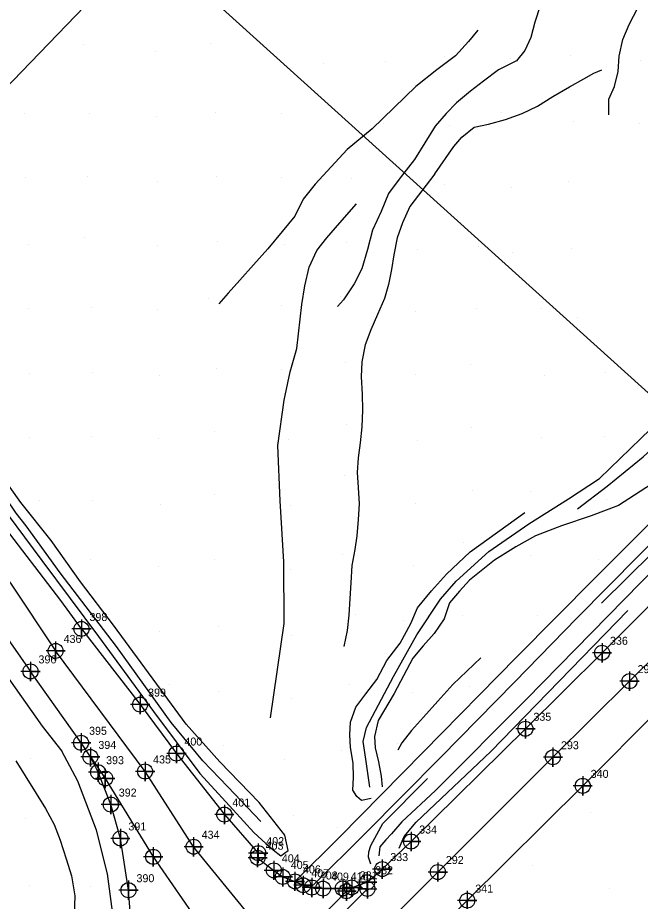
# Model space of a CAD drawing. Extents: x 1497074 to 1501343, y 481943 to 486114.
# Drawn here: x 1499153.8 to 1499348.3, y 485629.8 to 485905.8 of the extents above; entities that cross this region are included whole.
import ezdxf

# ---------------------------------------------------------------- set-up
doc = ezdxf.new("R2010")
doc.units = 0
for name, color, linetype in [('Exist DTM Breakline', 7, 'Continuous'), ('Exist DTM Breakline Cogo Point CELL', 7, 'Continuous'), ('Exist DTM Crownline', 7, 'Continuous'), ('Exist DTM Crownline Cogo Number', 7, 'Continuous'), ('Exist DTM Crownline Cogo Point CELL', 7, 'Continuous'), ('Exist Roads EOP', 7, 'Continuous'), ('Exist Roads EOP Cogo Number', 7, 'Continuous'), ('Exist Roads EOP Cogo Point CELL', 7, 'Continuous'), ('Exist Roads EOT', 7, 'Continuous'), ('Exist Roads EOT Cogo Point CELL', 7, 'Continuous'), ('PH Exist DTM Boundary', 7, 'Continuous'), ('PH Exist DTM Breakline', 7, 'Continuous'), ('PH Exist DTM Point', 7, 'Continuous')]:
    doc.layers.add(name, color=color, linetype=linetype)

msp = doc.modelspace()

# ---------------------------------------------------------------- linework, layer by layer
at = {"layer": 'Exist DTM Breakline'}
for points in [[(1499176.46, 485674.88), (1499181.12, 485668.19), (1499196.1, 485643.7), (1499211.18, 485621.88)], [(1499222.35, 485598.56), (1499236.31, 485612.27), (1499256.47, 485632.94)]]:
    msp.add_lwpolyline(points, dxfattribs=at)
at = {"layer": 'Exist DTM Breakline Cogo Point CELL'}
for points in [[(1499181.12, 485671.19), (1499181.12, 485665.19), (1499181.12, 485668.19), (1499184.12, 485668.19), (1499178.12, 485668.19)], [(1499196.1, 485646.7), (1499196.1, 485640.7), (1499196.1, 485643.7), (1499199.1, 485643.7), (1499193.1, 485643.7)], [(1499256.47, 485635.94), (1499256.47, 485629.94), (1499256.47, 485632.94), (1499259.47, 485632.94), (1499253.47, 485632.94)]]:
    msp.add_lwpolyline(points, dxfattribs=at)
for centre in [(1499181.12, 485668.19), (1499196.1, 485643.7), (1499256.47, 485632.94)]:
    msp.add_circle(centre, 2.34, dxfattribs=at)
at = {"layer": 'Exist DTM Crownline'}
for points in [[(1498753.92, 485018.83), (1498767.97, 485036.35), (1498784.41, 485057.61), (1498813.33, 485094.71), (1498845.11, 485135.39), (1498876.05, 485175.22), (1498907.7, 485215.72), (1498939.87, 485257.15), (1498970.73, 485296.32), (1499001.6, 485335.5), (1499032.55, 485374.36), (1499053.88, 485400.5), (1499073.91, 485423.48), (1499090.49, 485441.64), (1499112.37, 485464.57), (1499148.43, 485501.47), (1499184.54, 485537.77), (1499215.93, 485569.25), (1499248.51, 485602.52), (1499285.02, 485638.96), (1499320.99, 485674.8), (1499344.91, 485698.57), (1499374.04, 485727.35), (1499398.21, 485750.96)], [(1499235.5, 485614.5), (1499226.83, 485624.63), (1499208.73, 485646.85), (1499193.56, 485670.36), (1499165.61, 485707.99)]]:
    msp.add_lwpolyline(points, dxfattribs=at)
at = {"layer": 'Exist DTM Crownline Cogo Point CELL'}
for points in [[(1499165.61, 485710.99), (1499165.61, 485704.99), (1499165.61, 485707.99), (1499168.61, 485707.99), (1499162.61, 485707.99)], [(1499344.91, 485701.57), (1499344.91, 485695.57), (1499344.91, 485698.57), (1499347.91, 485698.57), (1499341.91, 485698.57)], [(1499320.99, 485677.8), (1499320.99, 485671.8), (1499320.99, 485674.8), (1499323.99, 485674.8), (1499317.99, 485674.8)], [(1499193.56, 485673.36), (1499193.56, 485667.36), (1499193.56, 485670.36), (1499196.56, 485670.36), (1499190.56, 485670.36)], [(1499208.73, 485649.85), (1499208.73, 485643.85), (1499208.73, 485646.85), (1499211.73, 485646.85), (1499205.73, 485646.85)], [(1499285.02, 485641.96), (1499285.02, 485635.96), (1499285.02, 485638.96), (1499288.02, 485638.96), (1499282.02, 485638.96)]]:
    msp.add_lwpolyline(points, dxfattribs=at)
for centre in [(1499165.61, 485707.99), (1499344.91, 485698.57), (1499320.99, 485674.8), (1499193.56, 485670.36), (1499208.73, 485646.85), (1499285.02, 485638.96)]:
    msp.add_circle(centre, 2.34, dxfattribs=at)
at = {"layer": 'Exist Roads EOP'}
for points in [[(1499258.1, 485634.16), (1499262.94, 485635.76), (1499267.66, 485639.88), (1499276.68, 485648.48), (1499312.38, 485683.69), (1499336.31, 485707.42), (1499365.12, 485736.27), (1499388.62, 485759.64)], [(1499406.68, 485742.77), (1499382.28, 485717.88), (1499354.16, 485689.77), (1499330.28, 485665.86), (1499294.21, 485630.03), (1499257.75, 485593.24), (1499238.22, 485573.68), (1499232.58, 485566.91), (1499223.56, 485558.73), (1499194.15, 485529.24), (1499157.4, 485492.59), (1499121.26, 485455.44)], [(1499173.68, 485714.85), (1499192, 485691.24), (1499203.35, 485675.95), (1499218.32, 485656.9), (1499228.92, 485644.84), (1499228.72, 485643.43), (1499233.78, 485639.48), (1499236.57, 485637.41), (1499240.39, 485636.03), (1499242.98, 485634.81), (1499245.65, 485634.12), (1499249.15, 485633.78), (1499255.31, 485633.84), (1499258.1, 485634.16)], [(1499172.31, 485548.88), (1499179.71, 485562.65), (1499184.8, 485580.27), (1499188.78, 485607.06), (1499189.23, 485622.67), (1499188.38, 485633.27), (1499185.84, 485649.44), (1499182.84, 485660.02), (1499178.88, 485670.13), (1499176.46, 485674.89), (1499173.56, 485679.31), (1499157.76, 485701.6)]]:
    msp.add_lwpolyline(points, dxfattribs=at)
at = {"layer": 'Exist Roads EOP Cogo Point CELL'}
for points in [[(1499173.68, 485717.85), (1499173.68, 485711.85), (1499173.68, 485714.85), (1499176.68, 485714.85), (1499170.68, 485714.85)], [(1499336.31, 485710.42), (1499336.31, 485704.42), (1499336.31, 485707.42), (1499339.31, 485707.42), (1499333.31, 485707.42)], [(1499157.76, 485704.6), (1499157.76, 485698.6), (1499157.76, 485701.6), (1499160.76, 485701.6), (1499154.76, 485701.6)], [(1499192, 485694.24), (1499192, 485688.24), (1499192, 485691.24), (1499195, 485691.24), (1499189, 485691.24)], [(1499312.38, 485686.69), (1499312.38, 485680.69), (1499312.38, 485683.69), (1499315.38, 485683.69), (1499309.38, 485683.69)], [(1499173.56, 485682.31), (1499173.56, 485676.31), (1499173.56, 485679.31), (1499176.56, 485679.31), (1499170.56, 485679.31)], [(1499176.46, 485677.89), (1499176.46, 485671.89), (1499176.46, 485674.89), (1499179.46, 485674.89), (1499173.46, 485674.89)], [(1499203.35, 485678.95), (1499203.35, 485672.95), (1499203.35, 485675.95), (1499206.35, 485675.95), (1499200.35, 485675.95)], [(1499178.88, 485673.13), (1499178.88, 485667.13), (1499178.88, 485670.13), (1499181.88, 485670.13), (1499175.88, 485670.13)], [(1499330.28, 485668.86), (1499330.28, 485662.86), (1499330.28, 485665.86), (1499333.28, 485665.86), (1499327.28, 485665.86)], [(1499182.84, 485663.02), (1499182.84, 485657.02), (1499182.84, 485660.02), (1499185.84, 485660.02), (1499179.84, 485660.02)], [(1499218.32, 485659.9), (1499218.32, 485653.9), (1499218.32, 485656.9), (1499221.32, 485656.9), (1499215.32, 485656.9)], [(1499185.84, 485652.44), (1499185.84, 485646.44), (1499185.84, 485649.44), (1499188.84, 485649.44), (1499182.84, 485649.44)], [(1499276.68, 485651.48), (1499276.68, 485645.48), (1499276.68, 485648.48), (1499279.68, 485648.48), (1499273.68, 485648.48)], [(1499228.92, 485647.84), (1499228.92, 485641.84), (1499228.92, 485644.84), (1499231.92, 485644.84), (1499225.92, 485644.84)], [(1499228.72, 485646.43), (1499228.72, 485640.43), (1499228.72, 485643.43), (1499231.72, 485643.43), (1499225.72, 485643.43)], [(1499233.78, 485642.48), (1499233.78, 485636.48), (1499233.78, 485639.48), (1499236.78, 485639.48), (1499230.78, 485639.48)], [(1499267.66, 485642.88), (1499267.66, 485636.88), (1499267.66, 485639.88), (1499270.66, 485639.88), (1499264.66, 485639.88)], [(1499236.57, 485640.41), (1499236.57, 485634.41), (1499236.57, 485637.41), (1499239.57, 485637.41), (1499233.57, 485637.41)], [(1499240.39, 485639.03), (1499240.39, 485633.03), (1499240.39, 485636.03), (1499243.39, 485636.03), (1499237.39, 485636.03)], [(1499188.38, 485636.27), (1499188.38, 485630.27), (1499188.38, 485633.27), (1499191.38, 485633.27), (1499185.38, 485633.27)], [(1499242.98, 485637.81), (1499242.98, 485631.81), (1499242.98, 485634.81), (1499245.98, 485634.81), (1499239.98, 485634.81)], [(1499245.65, 485637.12), (1499245.65, 485631.12), (1499245.65, 485634.12), (1499248.65, 485634.12), (1499242.65, 485634.12)], [(1499249.15, 485636.78), (1499249.15, 485630.78), (1499249.15, 485633.78), (1499252.15, 485633.78), (1499246.15, 485633.78)], [(1499255.31, 485636.84), (1499255.31, 485630.84), (1499255.31, 485633.84), (1499258.31, 485633.84), (1499252.31, 485633.84)], [(1499258.1, 485637.16), (1499258.1, 485631.16), (1499258.1, 485634.16), (1499261.1, 485634.16), (1499255.1, 485634.16)], [(1499262.94, 485638.76), (1499262.94, 485632.76), (1499262.94, 485635.76), (1499265.94, 485635.76), (1499259.94, 485635.76)], [(1499294.21, 485633.03), (1499294.21, 485627.03), (1499294.21, 485630.03), (1499297.21, 485630.03), (1499291.21, 485630.03)]]:
    msp.add_lwpolyline(points, dxfattribs=at)
for centre in [(1499173.68, 485714.85), (1499336.31, 485707.42), (1499157.76, 485701.6), (1499192, 485691.24), (1499312.38, 485683.69), (1499173.56, 485679.31), (1499203.35, 485675.95), (1499176.46, 485674.89), (1499178.88, 485670.13), (1499330.28, 485665.86), (1499182.84, 485660.02), (1499218.32, 485656.9), (1499185.84, 485649.44), (1499276.68, 485648.48), (1499228.92, 485644.84), (1499228.72, 485643.43), (1499233.78, 485639.48), (1499267.66, 485639.88), (1499236.57, 485637.41), (1499240.39, 485636.03), (1499242.98, 485634.81), (1499245.65, 485634.12), (1499249.15, 485633.78), (1499255.31, 485633.84), (1499258.1, 485634.16), (1499262.94, 485635.76), (1499188.38, 485633.27), (1499294.21, 485630.03)]:
    msp.add_circle(centre, 2.34, dxfattribs=at)
at = {"layer": 'Exist Roads EOT'}
msp.add_lwpolyline([(1499164.74, 485535.21), (1499193.9, 485564.62), (1499219.81, 485590.53), (1499263, 485633.7)], dxfattribs=at)
at = {"layer": 'Exist Roads EOT Cogo Point CELL'}
msp.add_lwpolyline([(1499263, 485636.7), (1499263, 485630.7), (1499263, 485633.7), (1499260, 485633.7), (1499266, 485633.7)], dxfattribs=at)
msp.add_circle((1499263, 485633.7), 2.34, dxfattribs=at)
at = {"layer": 'PH Exist DTM Boundary'}
for points in [[(1499194.3, 485929.74), (1499565.8, 485594.67), (1499665.72, 485698.27), (1499305.84, 486045.38)], [(1498846.5, 485569.16), (1499227.59, 485244.03), (1499565.8, 485594.67), (1499194.3, 485929.74)]]:
    msp.add_lwpolyline(points, close=True, dxfattribs=at)
at = {"layer": 'PH Exist DTM Breakline'}
for points in [[(1499338.41, 485875.42), (1499338.43, 485880.26), (1499340.17, 485884.29), (1499341.34, 485888.91), (1499341.71, 485893.71), (1499342.78, 485898.91), (1499344.79, 485903.6), (1499347.49, 485908.81), (1499351.23, 485915.07), (1499354.84, 485920.58), (1499359.06, 485926.29), (1499363.76, 485931.87), (1499368.81, 485937.66), (1499373.27, 485942.79), (1499377.18, 485947.28)], [(1499327.33, 485933.42), (1499326.69, 485928.46), (1499325.21, 485923.81), (1499322.6, 485918.77), (1499319.45, 485913.65), (1499316.97, 485909.47), (1499315.29, 485904.37), (1499314.03, 485899.55), (1499312.24, 485895.47), (1499309.58, 485892.31), (1499304.01, 485889.43), (1499299.24, 485885.89), (1499295.19, 485882.76), (1499290.86, 485879.21), (1499287.61, 485875.84), (1499284.17, 485871.89), (1499277.77, 485861.5)], [(1499297.54, 485901.82), (1499294.61, 485898.27), (1499290.49, 485893.86), (1499284.66, 485889.47), (1499278.17, 485884.27), (1499264.46, 485871.05)], [(1499284.13, 485856.97), (1499289.98, 485865.49), (1499292.51, 485868.39), (1499296.34, 485871.54), (1499300.82, 485872.52), (1499306.12, 485873.92), (1499311.4, 485875.83), (1499316.13, 485878.07), (1499320.94, 485881.15), (1499326.14, 485884.16), (1499330.62, 485886.7), (1499333.76, 485888.47), (1499336.25, 485889.5)], [(1499264.46, 485871.05), (1499256.72, 485864.62), (1499246.72, 485853.79), (1499242.93, 485849.11), (1499240.3, 485843.72), (1499236.34, 485838.99), (1499231.9, 485833.59), (1499227.48, 485828.61), (1499223.21, 485823.83), (1499219.55, 485819.73), (1499216.61, 485816.44)], [(1499277.77, 485861.5), (1499273.21, 485855.76), (1499269.59, 485850.8), (1499267.33, 485845.23), (1499264.64, 485839.37), (1499263.05, 485833.35), (1499261.32, 485827.28), (1499258.85, 485822.61), (1499255.58, 485817.63), (1499253.7, 485815.51)], [(1499284.13, 485856.97), (1499276.25, 485846.82), (1499273.94, 485841.68), (1499272.31, 485836.96), (1499271.24, 485831.74), (1499270.54, 485827.07), (1499269.58, 485822.44), (1499268.39, 485818.07), (1499266.2, 485813.11), (1499264.05, 485808.3), (1499262.35, 485803.61), (1499261.26, 485798.26), (1499261.06, 485793.57), (1499261.33, 485788.15), (1499261.49, 485783.23), (1499261.28, 485778.01), (1499260.75, 485772.99), (1499260.17, 485768.34), (1499259.85, 485763.74), (1499260.12, 485759.01), (1499260.47, 485753.98), (1499260.13, 485749.09), (1499259.73, 485743.99), (1499259.11, 485739.65), (1499258.18, 485734.69), (1499257.8, 485729.26), (1499257.51, 485724.32), (1499257.21, 485719.2), (1499256.7, 485714.42), (1499255.62, 485709.34)], [(1499232.75, 485687.11), (1499236.96, 485716.58), (1499236.87, 485735.8), (1499235.81, 485754.83), (1499235.04, 485772.12), (1499237, 485786.31), (1499238.87, 485795.11), (1499240.93, 485802.43), (1499242.51, 485816.15), (1499243.42, 485822.06), (1499244.78, 485827.84), (1499247.17, 485833.08), (1499250.31, 485837.03), (1499254.45, 485841.67), (1499259.63, 485847.61)], [(1499229.71, 485654.73), (1499219.4, 485665.56), (1499211.63, 485673.64), (1499201.76, 485685.6), (1499184.63, 485709.35), (1499167.01, 485732.42), (1499156.46, 485747.1), (1499153.27, 485751), (1499146.89, 485760.3), (1499132.38, 485780.87), (1499119.27, 485800.79), (1499104.73, 485823.72), (1499094.44, 485837.33)], [(1499173.68, 485714.85), (1499167.19, 485723.77), (1499148.64, 485748.11), (1499130.51, 485772.13), (1499116, 485791.04), (1499097.67, 485814.77), (1499085.19, 485830.54)], [(1499077.06, 485824.55), (1499092.45, 485805.28), (1499108.65, 485784.4), (1499127.38, 485760.11), (1499151.53, 485729.14), (1499165.61, 485707.99)], [(1499068.97, 485817.49), (1499083.05, 485799.83), (1499099.09, 485779.44), (1499114.5, 485759.1), (1499129.89, 485739.82), (1499148.38, 485715), (1499157.76, 485701.6)], [(1499263.77, 485665.44), (1499262.49, 485674.17), (1499261.7, 485679.68), (1499262.71, 485684.08), (1499271.15, 485700.06), (1499278.47, 485713.07), (1499285.81, 485724.17), (1499290.79, 485729.75), (1499300.92, 485739.04), (1499313.47, 485747.72), (1499325.83, 485755.49), (1499335.56, 485761.87), (1499348.39, 485774.33), (1499360.19, 485785.69), (1499365.26, 485790.69)], [(1499328.66, 485752.34), (1499337.96, 485759.47), (1499349.18, 485768.58), (1499359.28, 485777.86), (1499366.41, 485784.67)], [(1499373.87, 485780.29), (1499353.21, 485761.01), (1499341.44, 485753.44), (1499332.9, 485750.22), (1499323.66, 485747.02), (1499315.58, 485743.93), (1499309.41, 485740.52), (1499302.75, 485736.38), (1499294.89, 485730.11), (1499291.82, 485726.68), (1499288.66, 485723.02), (1499286.96, 485718.06), (1499283.92, 485713.48), (1499280.48, 485709.62), (1499277.23, 485705.77), (1499271.39, 485694.69), (1499266.38, 485686.26), (1499265.24, 485681.28), (1499265.46, 485677.78), (1499266.5, 485673.41), (1499267.31, 485668.86), (1499267.59, 485665.59)], [(1499377.52, 485774.37), (1499356.71, 485753.35), (1499334.21, 485730.82), (1499309.75, 485706.2), (1499280.46, 485676.39), (1499254.43, 485649.91), (1499240.48, 485636.07)], [(1499145.27, 485757.67), (1499161.28, 485736.27), (1499179.04, 485712.53), (1499196.18, 485689.05), (1499210.64, 485669.68), (1499221.03, 485658.39), (1499227.54, 485651.26), (1499231.29, 485647.91), (1499233.53, 485645.91), (1499236.01, 485643.98), (1499238.21, 485645.65), (1499237.23, 485650.46), (1499229.16, 485660.65), (1499216.9, 485673.4), (1499206.35, 485685.12), (1499197.22, 485697.58), (1499183.7, 485716.02), (1499173.39, 485729.55), (1499164.23, 485742.44), (1499154.78, 485754.38), (1499141.8, 485772.4)], [(1499246.03, 485634.9), (1499262.18, 485650.84), (1499285.92, 485674.84), (1499308.93, 485698.23), (1499328.52, 485718.3), (1499347.84, 485737.84), (1499368.19, 485758.34), (1499381.05, 485771.3)], [(1499381.7, 485766.98), (1499360.14, 485746.52), (1499336.2, 485722.89)], [(1499383.77, 485765.01), (1499353.48, 485734.44), (1499312.69, 485692.97), (1499284.3, 485664.38), (1499273.79, 485654.58), (1499270.53, 485650.93), (1499268.82, 485649.01), (1499266.93, 485646.77), (1499266.57, 485644.06)], [(1499264.15, 485661.96), (1499261.2, 485661.32), (1499259.75, 485662.5), (1499258.46, 485664.56), (1499258.71, 485668.44), (1499258.61, 485672.96), (1499257.75, 485677.8), (1499257.52, 485681.75), (1499257.71, 485685.75), (1499259.36, 485690.44), (1499262.48, 485694.63), (1499265.98, 485699.1), (1499269.09, 485705.06), (1499273.23, 485710.39), (1499276.57, 485716.59), (1499278.64, 485721.42), (1499283, 485726.72), (1499287.71, 485731.99), (1499295.08, 485738.92), (1499312.24, 485751.18)], [(1499125.55, 485735.22), (1499161.44, 485684.5), (1499167.54, 485676.72)], [(1499272.91, 485646.45), (1499274.48, 485650.08), (1499278.3, 485654.49), (1499301.54, 485676.58), (1499344.35, 485720.67)], [(1499298.41, 485705.89), (1499289.66, 485697.52), (1499284.98, 485692.27), (1499280.57, 485687.33), (1499276.8, 485683.12), (1499273.79, 485679.31), (1499272.56, 485677.04)], [(1499177.87, 485578.72), (1499178.98, 485584.56), (1499179.92, 485588.38), (1499181.37, 485590.01), (1499183.81, 485596.7), (1499183.46, 485616.03), (1499183.43, 485626.6), (1499181.81, 485638.44), (1499178.36, 485652.05), (1499172.58, 485667.36), (1499167.54, 485676.72)], [(1499153.17, 485673.71), (1499162.45, 485658.84), (1499165.18, 485653.77), (1499167.02, 485648.89), (1499168.88, 485643.09), (1499170.56, 485637.72), (1499171.57, 485631.53), (1499171.4, 485625.48), (1499170.63, 485618.57), (1499170.84, 485611.93), (1499171.01, 485605.52), (1499171.2, 485599.72), (1499170.74, 485593.96), (1499169.59, 485586.49), (1499169.76, 485581.42), (1499170.2, 485576.57), (1499167.23, 485571.91), (1499158.21, 485562.48), (1499132.52, 485536.14)], [(1499264.07, 485641.38), (1499263.31, 485643.56), (1499263.44, 485645.29), (1499264.07, 485647.28), (1499267.83, 485654.09), (1499281.74, 485668.16)]]:
    msp.add_lwpolyline(points, dxfattribs=at)
at = {"layer": 'PH Exist DTM Point'}
for p, q in [((1499174.39, 485897.39), (1499174.39, 485897.39)), ((1499214.12, 485897.63), (1499214.12, 485897.63)), ((1499196.83, 485895.21), (1499196.83, 485895.21)), ((1499286.98, 485893.61), (1499286.98, 485893.61)), ((1499307.6, 485893.07), (1499307.6, 485893.07)), ((1499326.49, 485894.06), (1499326.49, 485894.06)), ((1499249.38, 485891.5), (1499249.38, 485891.5)), ((1499268.63, 485892.17), (1499268.63, 485892.17)), ((1499348.25, 485892.51), (1499348.25, 485892.51)), ((1499215.67, 485876.23), (1499215.67, 485876.23)), ((1499156.04, 485875.92), (1499156.04, 485875.92)), ((1499176.04, 485875.92), (1499176.04, 485875.92)), ((1499197.08, 485874.99), (1499197.08, 485874.99)), ((1499236.04, 485875.92), (1499236.04, 485875.92)), ((1499304.84, 485876.01), (1499304.84, 485876.01)), ((1499268.2, 485872.55), (1499268.2, 485872.55)), ((1499288.66, 485872.15), (1499288.66, 485872.15)), ((1499327.28, 485873.42), (1499327.28, 485873.42)), ((1499348.05, 485872.68), (1499348.05, 485872.68)), ((1499156.26, 485855.72), (1499156.26, 485855.72)), ((1499175.6, 485856.31), (1499175.6, 485856.31)), ((1499197.43, 485854.68), (1499197.43, 485854.68)), ((1499215.88, 485856.06), (1499215.88, 485856.06)), ((1499236.04, 485855.92), (1499236.04, 485855.92)), ((1499258.09, 485855.67), (1499258.09, 485855.67)), ((1499276.7, 485855.33), (1499276.7, 485855.33)), ((1499325.88, 485854.57), (1499325.88, 485854.57)), ((1499287.04, 485853.56), (1499287.04, 485853.56)), ((1499307.96, 485852.76), (1499307.96, 485852.76)), ((1499157.18, 485834.9), (1499157.18, 485834.9)), ((1499174.73, 485837.09), (1499174.73, 485837.09)), ((1499216.03, 485835.92), (1499216.03, 485835.92)), ((1499237, 485835.06), (1499237, 485835.06)), ((1499256.5, 485835.56), (1499256.5, 485835.56)), ((1499197.35, 485834.74), (1499197.35, 485834.74)), ((1499278.78, 485833.47), (1499278.78, 485833.47)), ((1499297.82, 485834.33), (1499297.82, 485834.33)), ((1499308.42, 485832.36), (1499308.42, 485832.36)), ((1499326.92, 485833.66), (1499326.92, 485833.66)), ((1499254.49, 485818.66), (1499254.49, 485818.66)), ((1499213.47, 485818.21), (1499213.47, 485818.21)), ((1499236.04, 485815.92), (1499236.04, 485815.92)), ((1499157.2, 485814.88), (1499157.2, 485814.88)), ((1499176.81, 485815.23), (1499176.81, 485815.23)), ((1499197.44, 485814.67), (1499197.44, 485814.67)), ((1499278.12, 485814.05), (1499278.12, 485814.05)), ((1499297.13, 485814.97), (1499297.13, 485814.97)), ((1499317.28, 485814.81), (1499317.28, 485814.81)), ((1499328.58, 485812.22), (1499328.58, 485812.22)), ((1499256.3, 485798.02), (1499256.3, 485798.02)), ((1499295.18, 485797.45), (1499295.18, 485797.45)), ((1499157.56, 485794.56), (1499157.56, 485794.56)), ((1499177.14, 485794.93), (1499177.14, 485794.93)), ((1499198.03, 485794.14), (1499198.03, 485794.14)), ((1499215.83, 485796.1), (1499215.83, 485796.1)), ((1499236.06, 485795.9), (1499236.06, 485795.9)), ((1499277.98, 485794.18), (1499277.98, 485794.18)), ((1499318.3, 485793.9), (1499318.3, 485793.9)), ((1499337.37, 485794.9), (1499337.37, 485794.9)), ((1499256.35, 485778.57), (1499256.35, 485778.57)), ((1499295.62, 485777.8), (1499295.62, 485777.8)), ((1499157.49, 485774.63), (1499157.49, 485774.63)), ((1499176.94, 485775.11), (1499176.94, 485775.11)), ((1499197.63, 485774.49), (1499197.63, 485774.49)), ((1499215.21, 485776.67), (1499215.21, 485776.67)), ((1499317.46, 485774.65), (1499317.46, 485774.65)), ((1499337.2, 485774.88), (1499337.2, 485774.88)), ((1499238.25, 485773.89), (1499238.25, 485773.89)), ((1499278.67, 485773.57), (1499278.67, 485773.57)), ((1499255.89, 485762.64), (1499255.89, 485762.64)), ((1499295.85, 485758), (1499295.85, 485758)), ((1499313.99, 485757.74), (1499313.99, 485757.74)), ((1499160.56, 485755.09), (1499160.56, 485755.09)), ((1499177.18, 485754.9), (1499177.18, 485754.9)), ((1499215.14, 485756.72), (1499215.14, 485756.72)), ((1499337.69, 485755.33), (1499337.69, 485755.33)), ((1499198.42, 485753.79), (1499198.42, 485753.79)), ((1499238.95, 485753.32), (1499238.95, 485753.32)), ((1499278.11, 485754.06), (1499278.11, 485754.06)), ((1499293.13, 485741.72), (1499293.13, 485741.72)), ((1499176.44, 485736.44), (1499176.44, 485736.44)), ((1499215.27, 485736.6), (1499215.27, 485736.6)), ((1499255.26, 485738.05), (1499255.26, 485738.05)), ((1499314.02, 485737.72), (1499314.02, 485737.72)), ((1499335.2, 485736.67), (1499335.2, 485736.67)), ((1499197.81, 485734.33), (1499197.81, 485734.33)), ((1499238.97, 485733.3), (1499238.97, 485733.3)), ((1499277.41, 485734.69), (1499277.41, 485734.69)), ((1499259.24, 485719.5), (1499259.24, 485719.5)), ((1499292.68, 485718.99), (1499292.68, 485718.99)), ((1499316.27, 485719.1), (1499316.27, 485719.1)), ((1499274.18, 485717.58), (1499274.18, 485717.58)), ((1499198.15, 485714.03), (1499198.15, 485714.03)), ((1499216.37, 485715.62), (1499216.37, 485715.62)), ((1499239.34, 485712.97), (1499239.34, 485712.97)), ((1499201.12, 485697.56), (1499201.12, 485697.56)), ((1499257.42, 485697.57), (1499257.42, 485697.57)), ((1499295, 485696.84), (1499295, 485696.84)), ((1499216.59, 485695.43), (1499216.59, 485695.43)), ((1499277.13, 485694.94), (1499277.13, 485694.94)), ((1499239.27, 485693.03), (1499239.27, 485693.03)), ((1499218.2, 485678.34), (1499218.2, 485678.34)), ((1499272.5, 485679.08), (1499272.5, 485679.08)), ((1499254.87, 485676.96), (1499254.87, 485676.96)), ((1499157.66, 485674.47), (1499157.66, 485674.47)), ((1499237.18, 485674.19), (1499237.18, 485674.19)), ((1499156.25, 485655.72), (1499156.25, 485655.72)), ((1499239.91, 485656.55), (1499239.91, 485656.55)), ((1499332.6, 485657.63), (1499332.6, 485657.63)), ((1499253.81, 485652.84), (1499253.81, 485652.84)), ((1499240.1, 485640.46), (1499240.1, 485640.46)), ((1499314.66, 485640.96), (1499314.66, 485640.96)), ((1499157.36, 485634.74), (1499157.36, 485634.74)), ((1499176.6, 485634.56), (1499176.6, 485634.56)), ((1499338.61, 485633.9), (1499338.61, 485633.9))]:
    msp.add_line(p, q, dxfattribs=at)

# ---------------------------------------------------------------- texts
at = {"layer": 'Exist DTM Crownline Cogo Number'}
for s, p in [('436', (1499168.11, 485710.49)), ('294', (1499347.41, 485701.07)), ('293', (1499323.49, 485677.3)), ('435', (1499196.06, 485672.86)), ('434', (1499211.23, 485649.35)), ('292', (1499287.52, 485641.46))]:
    msp.add_text(s, height=2.5, dxfattribs=at).set_placement(p)
at = {"layer": 'Exist Roads EOP Cogo Number'}
for s, p in [('398', (1499176.18, 485717.35)), ('336', (1499338.81, 485709.92)), ('396', (1499160.26, 485704.1)), ('399', (1499194.5, 485693.74)), ('335', (1499314.88, 485686.19)), ('395', (1499176.06, 485681.81)), ('400', (1499205.85, 485678.45)), ('394', (1499178.96, 485677.39)), ('393', (1499181.38, 485672.63)), ('340', (1499332.78, 485668.36)), ('392', (1499185.34, 485662.52)), ('401', (1499220.82, 485659.4)), ('391', (1499188.34, 485651.94)), ('334', (1499279.18, 485650.98)), ('403', (1499231.22, 485645.93)), ('402', (1499231.42, 485647.34)), ('404', (1499236.28, 485641.98)), ('333', (1499270.16, 485642.38)), ('405', (1499239.07, 485639.91)), ('406', (1499242.89, 485638.53)), ('407', (1499245.48, 485637.31)), ('408', (1499248.15, 485636.62)), ('410', (1499257.81, 485636.34)), ('331', (1499260.6, 485636.67)), ('332', (1499265.44, 485638.26)), ('390', (1499190.88, 485635.77)), ('409', (1499251.65, 485636.28)), ('341', (1499296.71, 485632.53))]:
    msp.add_text(s, height=2.5, dxfattribs=at).set_placement(p)

doc.saveas('drawing.dxf')
